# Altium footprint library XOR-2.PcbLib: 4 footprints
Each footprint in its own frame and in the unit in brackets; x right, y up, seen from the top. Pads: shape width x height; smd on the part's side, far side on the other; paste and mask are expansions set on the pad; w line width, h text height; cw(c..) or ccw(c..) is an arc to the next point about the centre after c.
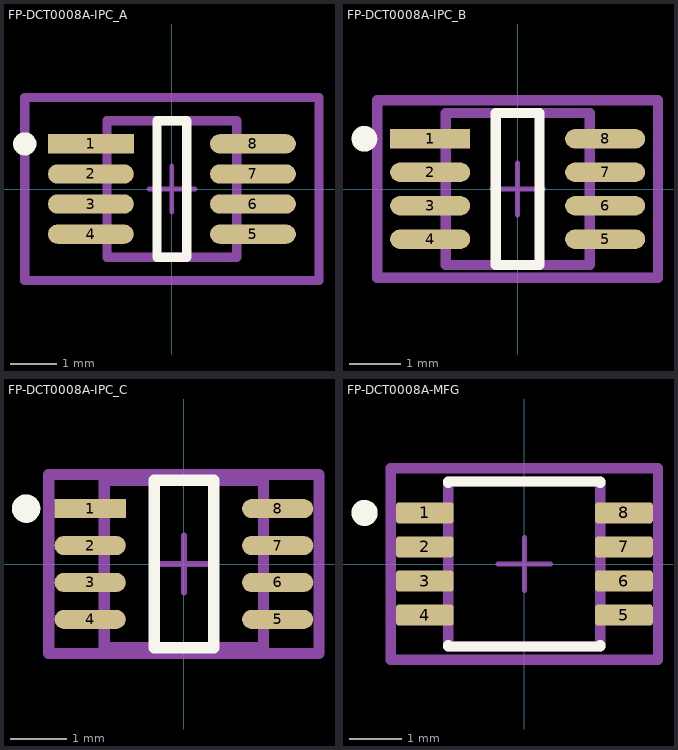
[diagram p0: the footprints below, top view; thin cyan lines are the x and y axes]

## FP-DCT0008A-IPC_A [mm]
pads (8):
  rect 1.854x0.416 smd paste+0 mask+0: 1(-1.75,0.975)
  rrect100% 1.854x0.416 smd paste+0 mask+0: 2(-1.75,0.325) 3(-1.75,-0.325) 4(-1.75,-0.975) 5(1.75,-0.975) 6(1.75,-0.325) 7(1.75,0.325) 8(1.75,0.975)
Top Overlay:
  circle w0.25: c-3.177,0.975 r0.125
  lines w0.2: -0.323,-1.475 0.323,-1.475 0.323,1.475 -0.323,1.475 -0.323,-1.475
Top Assembly:
  lines w0.2: -3.177,-1.975 3.177,-1.975 3.177,1.975 -3.177,1.975 -3.177,-1.975
  text ".Designator" at 0,0.188 h1
Top 3D Body:
  lines w0.2: -1.4,-1.475 1.4,-1.475 1.4,1.475 -1.4,1.475 -1.4,-1.475
Top Courtyard:
  lines w0.2: -3.177,-1.975 3.177,-1.975 3.177,1.975 -3.177,1.975 -3.177,-1.975
Top Component Center:
  lines w0.1: -0.5,0 0.5,0 ; 0,-0.5 0,0.5

## FP-DCT0008A-IPC_B [mm]
pads (8):
  rect 1.554x0.376 smd paste+0 mask+0: 1(-1.7,0.975)
  rrect100% 1.554x0.376 smd paste+0 mask+0: 2(-1.7,0.325) 3(-1.7,-0.325) 4(-1.7,-0.975) 5(1.7,-0.975) 6(1.7,-0.325) 7(1.7,0.325) 8(1.7,0.975)
Top Overlay:
  circle w0.25: c-2.977,0.975 r0.125
  lines w0.2: -0.423,-1.475 0.423,-1.475 0.423,1.475 -0.423,1.475 -0.423,-1.475
Top Assembly:
  lines w0.2: -2.727,-1.725 2.727,-1.725 2.727,1.725 -2.727,1.725 -2.727,-1.725
  text ".Designator" at 0,0.188 h1
Top 3D Body:
  lines w0.2: -1.4,-1.475 1.4,-1.475 1.4,1.475 -1.4,1.475 -1.4,-1.475
Top Courtyard:
  lines w0.2: -2.727,-1.725 2.727,-1.725 2.727,1.725 -2.727,1.725 -2.727,-1.725
Top Component Center:
  lines w0.1: -0.5,0 0.5,0 ; 0,-0.5 0,0.5

## FP-DCT0008A-IPC_C [mm]
pads (8):
  rect 1.254x0.336 smd paste+0 mask+0: 1(-1.65,0.975)
  rrect100% 1.254x0.336 smd paste+0 mask+0: 2(-1.65,0.325) 3(-1.65,-0.325) 4(-1.65,-0.975) 5(1.65,-0.975) 6(1.65,-0.325) 7(1.65,0.325) 8(1.65,0.975)
Top Overlay:
  circle w0.25: c-2.777,0.975 r0.125
  lines w0.2: -0.523,-1.475 0.523,-1.475 0.523,1.475 -0.523,1.475 -0.523,-1.475
Top Assembly:
  lines w0.2: -2.377,-1.575 2.377,-1.575 2.377,1.575 -2.377,1.575 -2.377,-1.575
  text ".Designator" at 0,0.188 h1
Top 3D Body:
  lines w0.2: -1.4,-1.475 1.4,-1.475 1.4,1.475 -1.4,1.475 -1.4,-1.475
Top Courtyard:
  lines w0.2: -2.377,-1.575 2.377,-1.575 2.377,1.575 -2.377,1.575 -2.377,-1.575
Top Component Center:
  lines w0.1: -0.5,0 0.5,0 ; 0,-0.5 0,0.5

## FP-DCT0008A-MFG [mm]
pads (8):
  rrect25% 1.1x0.4 smd paste+0 mask+0: 1(-1.9,0.975) 2(-1.9,0.325) 3(-1.9,-0.325) 4(-1.9,-0.975) 5(1.9,-0.975) 6(1.9,-0.325) 7(1.9,0.325) 8(1.9,0.975)
Top Overlay:
  circle w0.25: c-3.052,0.975 r0.125
  lines w0.2: -1.45,-1.55 -1.45,-1.575 1.45,-1.575 1.45,-1.55 ; -1.45,1.55 -1.45,1.575 1.45,1.575 1.45,1.55
Top Assembly:
  lines w0.2: -2.55,-1.825 2.55,-1.825 2.55,1.825 -2.55,1.825 -2.55,-1.825
  text ".Designator" at 0,0.188 h1
Top 3D Body:
  lines w0.2: -1.45,-1.575 1.45,-1.575 1.45,1.575 -1.45,1.575 -1.45,-1.575
Top Courtyard:
  lines w0.2: -2.55,-1.825 2.55,-1.825 2.55,1.825 -2.55,1.825 -2.55,-1.825
Top Component Center:
  lines w0.1: -0.5,0 0.5,0 ; 0,-0.5 0,0.5
3D body "IC_Texas_Instruments_SN74LVC3G34DCTR_eec.STEP": height 0.25, standoff 0, extent -2.55,-1.825 2.55,1.825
